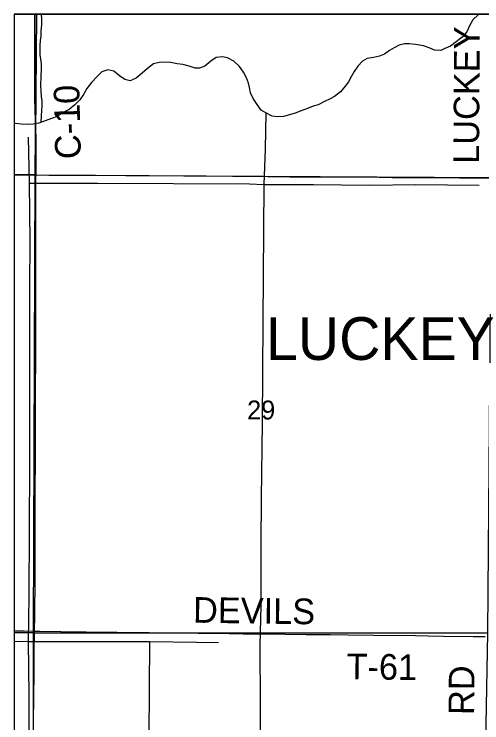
# Model space of a CAD drawing. Extents: x 0 to 34, y 0 to 22.
# Drawn here: x 2.1 to 3.136, y 19.331 to 20.9 of the extents above; entities that cross this region are included whole.
import ezdxf

# ---------------------------------------------------------------- set-up
doc = ezdxf.new("R2010")
doc.units = 0
for name, color, linetype in [('Default', 7, 'Continuous'), ('GM_X_Corporation_Text', 7, 'Continuous'), ('GM_X_County_Road', 7, 'Continuous'), ('GM_X_County_Road_Text', 7, 'Continuous'), ('GM_X_Major_River', 7, 'Continuous'), ('GM_X_Minor_River', 7, 'Continuous'), ('GM_X_Section', 7, 'Continuous'), ('GM_X_Section_Text', 7, 'Continuous'), ('GM_X_State_Route', 7, 'Continuous'), ('GM_X_Township_Road', 7, 'Continuous'), ('GM_X_Township_Road_Text', 7, 'Continuous'), ('SH_Cut_Line', 7, 'Continuous'), ('SH_Data', 7, 'Continuous')]:
    doc.layers.add(name, color=color, linetype=linetype)

msp = doc.modelspace()

# ---------------------------------------------------------------- linework, layer by layer
at = {"layer": 'Default'}
for points in [[(2.1495, 20.9), (2.1, 20.9), (2.1, 20.5449), (2.1468, 20.5444)], [(3.1581, 20.9), (2.1495, 20.9), (2.1468, 20.5444), (3.1572, 20.5385)], [(2.1, 20.5449), (2.1, 19.5304), (2.1432, 19.5299), (2.1468, 20.5444)], [(2.1, 19.5304), (2.1, 18.5238), (2.1261, 18.5235), (2.1356, 18.5238), (2.1418, 18.8909), (2.1432, 19.5299)]]:
    msp.add_lwpolyline(points, close=True, dxfattribs=at)
msp.add_lwpolyline([(3.1549, 20.9), (2.1, 20.9), (2.1, 15.5125)], dxfattribs=at)
at = {"layer": 'GM_X_County_Road'}
msp.add_lwpolyline([(2.1485, 20.5438), (2.1489, 20.5493), (2.149, 20.5509), (2.1491, 20.5529), (2.1491, 20.581), (2.1491, 20.604), (2.1488, 20.6215), (2.1478, 20.6482), (2.1463, 20.6861), (2.1455, 20.7178), (2.1457, 20.806), (2.1459, 20.8415), (2.1461, 20.8943), (2.1461, 20.9)], dxfattribs=at)
at = {"layer": 'GM_X_Major_River'}
for points in [[(3.1314, 20.9), (3.1285, 20.8985), (3.1165, 20.8871), (3.1102, 20.8755), (3.1034, 20.8612), (3.0932, 20.8493), (3.0797, 20.8386), (3.067, 20.8294), (3.0543, 20.8237), (3.0457, 20.8198), (3.0315, 20.8204), (3.0199, 20.8253), (3.0075, 20.8301), (2.9894, 20.8328), (2.9755, 20.8343), (2.9652, 20.8342), (2.9534, 20.8314), (2.9419, 20.8253), (2.9319, 20.8194), (2.9207, 20.8117), (2.91, 20.8071), (2.8963, 20.8043), (2.8826, 20.802), (2.8719, 20.7962), (2.8614, 20.7851), (2.8535, 20.7727), (2.8476, 20.7626), (2.8408, 20.7503), (2.8334, 20.7406), (2.8229, 20.7283), (2.8097, 20.718), (2.8001, 20.7126), (2.7875, 20.7068), (2.774, 20.6995), (2.7624, 20.6959)], [(2.7624, 20.6959), (2.7501, 20.6908), (2.7364, 20.6857), (2.723, 20.6807), (2.71, 20.6767), (2.6971, 20.6736), (2.6845, 20.6723), (2.6717, 20.6744), (2.6578, 20.6815), (2.6472, 20.687), (2.6384, 20.6998), (2.6295, 20.7129), (2.624, 20.7259), (2.6216, 20.7373), (2.6191, 20.7469), (2.6152, 20.7587), (2.6086, 20.7714), (2.5993, 20.7841), (2.5866, 20.7961), (2.5731, 20.8029), (2.5614, 20.8054), (2.5477, 20.8041), (2.5358, 20.796), (2.5227, 20.7848), (2.5104, 20.7805), (2.501, 20.7807), (2.4881, 20.7847), (2.4738, 20.7884), (2.4609, 20.7902), (2.4473, 20.7927), (2.4344, 20.7934), (2.4215, 20.7932), (2.4085, 20.7897), (2.3954, 20.78), (2.3835, 20.7692), (2.3707, 20.7581), (2.3574, 20.7526), (2.3453, 20.7555), (2.3333, 20.7637), (2.3209, 20.7735), (2.3077, 20.7764), (2.2943, 20.7721), (2.2831, 20.7613), (2.2711, 20.7486), (2.2614, 20.7351), (2.2536, 20.7223), (2.2454, 20.7103), (2.2346, 20.6989), (2.2218, 20.6887), (2.2088, 20.6821), (2.195, 20.6737), (2.1824, 20.669), (2.1686, 20.6635), (2.1548, 20.6585), (2.1419, 20.656), (2.1286, 20.6555), (2.1153, 20.6562), (2.1028, 20.6579), (2.1, 20.6584)]]:
    msp.add_lwpolyline(points, dxfattribs=at)
at = {"layer": 'GM_X_Minor_River'}
for points in [[(2.16, 20.6604), (2.1604, 20.6756), (2.1615, 20.6859), (2.1622, 20.698), (2.1621, 20.7083), (2.1609, 20.7178), (2.1597, 20.7304), (2.1593, 20.7422), (2.1599, 20.7627), (2.1607, 20.7779), (2.1603, 20.7905), (2.159, 20.8), (2.1578, 20.8099), (2.1577, 20.8194), (2.158, 20.8308), (2.1587, 20.8415), (2.1597, 20.8513), (2.1601, 20.8627), (2.1616, 20.8764), (2.1616, 20.8889), (2.1606, 20.9)], [(2.6578, 20.6815), (2.656, 20.601), (2.6537, 20.5231), (2.6512, 20.219), (2.6493, 19.9951), (2.6476, 19.8279), (2.6469, 19.7253), (2.6465, 19.5911), (2.6447, 19.5018), (2.6453, 19.3733), (2.6453, 19.2421), (2.6451, 19.1148), (2.6457, 18.9749), (2.6405, 18.7941), (2.6378, 18.6459), (2.6366, 18.5223)], [(2.1313, 20.6274), (2.1324, 20.5586), (2.1334, 20.5247), (2.1346, 20.3962), (2.1337, 20.2974), (2.1338, 20.1791), (2.1339, 20.0248), (2.1342, 19.9031), (2.1332, 19.759), (2.1327, 19.6112), (2.1314, 19.5105), (2.1326, 19.3918), (2.1324, 19.2804), (2.133, 19.1394), (2.1343, 19.0279), (2.1309, 18.8813), (2.1293, 18.7445), (2.1276, 18.6194), (2.1267, 18.5066)], [(2.1341, 20.5258), (2.2845, 20.5257), (2.4534, 20.5247), (2.6215, 20.5244), (2.6537, 20.5231), (2.7631, 20.523)], [(2.7631, 20.523), (2.8878, 20.5214), (2.9904, 20.5224), (3.1309, 20.5212)], [(2.1, 19.5113), (2.1007, 19.5113), (2.1314, 19.5105), (2.2191, 19.5106), (2.3144, 19.5105), (2.3998, 19.5107), (2.5041, 19.5093), (2.5531, 19.5082)], [(2.3998, 19.5107), (2.3987, 19.3005), (2.3964, 19.1797), (2.3942, 19.0623), (2.3933, 18.9361), (2.3913, 18.7875), (2.3878, 18.6253), (2.3861, 18.5364)]]:
    msp.add_lwpolyline(points, dxfattribs=at)
at = {"layer": 'GM_X_Section'}
for points in [[(3.1572, 20.5385), (3.1487, 19.529), (2.1432, 19.5299), (2.1468, 20.5444)], [(2.1432, 19.5299), (3.1487, 19.529), (3.1307, 18.5181), (3.1239, 18.5181), (2.1356, 18.5238), (2.1418, 18.8909)]]:
    msp.add_lwpolyline(points, close=True, dxfattribs=at)
at = {"layer": 'GM_X_State_Route'}
msp.add_lwpolyline([(2.1, 20.5438), (2.1112, 20.5438), (2.1485, 20.5438), (2.1765, 20.5436), (2.2806, 20.5431), (2.3474, 20.5429), (2.4764, 20.5419), (2.5836, 20.5412), (2.6629, 20.5405), (2.7111, 20.54), (2.7577, 20.5397), (2.8276, 20.5394), (2.9084, 20.5387), (2.9379, 20.5385), (3.0032, 20.538), (3.0871, 20.5376), (3.1306, 20.5373), (3.1528, 20.5377)], dxfattribs=at)
at = {"layer": 'GM_X_Township_Road'}
for points in [[(2.1452, 19.5337), (2.1453, 19.54), (2.1456, 19.563), (2.1459, 19.5904), (2.1463, 19.6277), (2.1465, 19.6812), (2.1465, 19.7465), (2.1467, 19.7887), (2.1466, 19.8217), (2.1469, 19.8621), (2.147, 19.8963), (2.1472, 19.9268), (2.1472, 19.9666), (2.1471, 20.0263), (2.1473, 20.0779), (2.1478, 20.1264), (2.1482, 20.1755), (2.1482, 20.244), (2.1482, 20.3186), (2.148, 20.3627), (2.148, 20.4262), (2.1482, 20.4691), (2.1483, 20.5114), (2.1482, 20.5352), (2.1482, 20.5369), (2.1482, 20.5384), (2.1485, 20.5438)], [(2.1, 19.5343), (2.1225, 19.534), (2.1452, 19.5337)], [(2.1377, 18.5216), (2.1375, 18.5293), (2.1372, 18.5386), (2.1373, 18.576), (2.1377, 18.6319), (2.1382, 18.691), (2.1386, 18.7376), (2.1393, 18.806), (2.1399, 18.8775), (2.14, 18.9086), (2.1411, 18.9832), (2.1416, 19.0142), (2.1418, 19.0391), (2.1418, 19.0982), (2.1419, 19.1355), (2.1414, 19.1883), (2.1411, 19.2194), (2.1418, 19.2847), (2.1427, 19.3344), (2.1434, 19.3841), (2.144, 19.4432), (2.1444, 19.4836), (2.1452, 19.5337)], [(2.1452, 19.5337), (2.1567, 19.5336), (2.2033, 19.5331), (2.2593, 19.5323), (2.3276, 19.5314), (2.3991, 19.5306), (2.4519, 19.5299), (2.5079, 19.5293), (2.5234, 19.5292), (2.5763, 19.5285), (2.6073, 19.528), (2.6167, 19.5279), (2.654, 19.5275), (2.7472, 19.5264), (2.8, 19.5258), (2.8404, 19.5254), (2.8964, 19.5247), (2.9896, 19.5236), (3.0176, 19.5232), (3.0518, 19.5227), (3.117, 19.522), (3.1419, 19.5219), (3.1438, 19.5218)]]:
    msp.add_lwpolyline(points, dxfattribs=at)
at = {"layer": 'SH_Cut_Line'}
msp.add_lwpolyline([(7.1734, 20.9), (2.1, 20.9), (2.1, 14.1)], dxfattribs=at)
at = {"layer": 'SH_Data'}
for q in [(2.1, 14.1), (8.9, 20.9)]:
    msp.add_line((2.1, 20.9), q, dxfattribs=at)

# ---------------------------------------------------------------- texts
at = {"layer": 'GM_X_Corporation_Text'}
msp.add_text('LUCKEY', height=0.0947, rotation=0, dxfattribs=at).set_placement((2.6584, 20.1342))
at = {"layer": 'GM_X_County_Road_Text'}
for s, rotation, p in [('LUCKEY', 89.6626, (3.1302, 20.5684)), ('C-10', 91.3251, (2.248, 20.5795)), ('RD', 89.5045, (3.1194, 19.3477))]:
    msp.add_text(s, height=0.05682, rotation=rotation, dxfattribs=at).set_placement(p)
at = {"layer": 'GM_X_Section_Text'}
msp.add_text('29', height=0.04186, rotation=0, dxfattribs=at).set_placement((2.6163, 20.0025))
at = {"layer": 'GM_X_Township_Road_Text'}
for s, rotation, p in [('DEVILS', 359.2281, (2.4963, 19.5523)), ('T-61', 359.2931, (2.8364, 19.4272))]:
    msp.add_text(s, height=0.05682, rotation=rotation, dxfattribs=at).set_placement(p)

doc.saveas('drawing.dxf')
